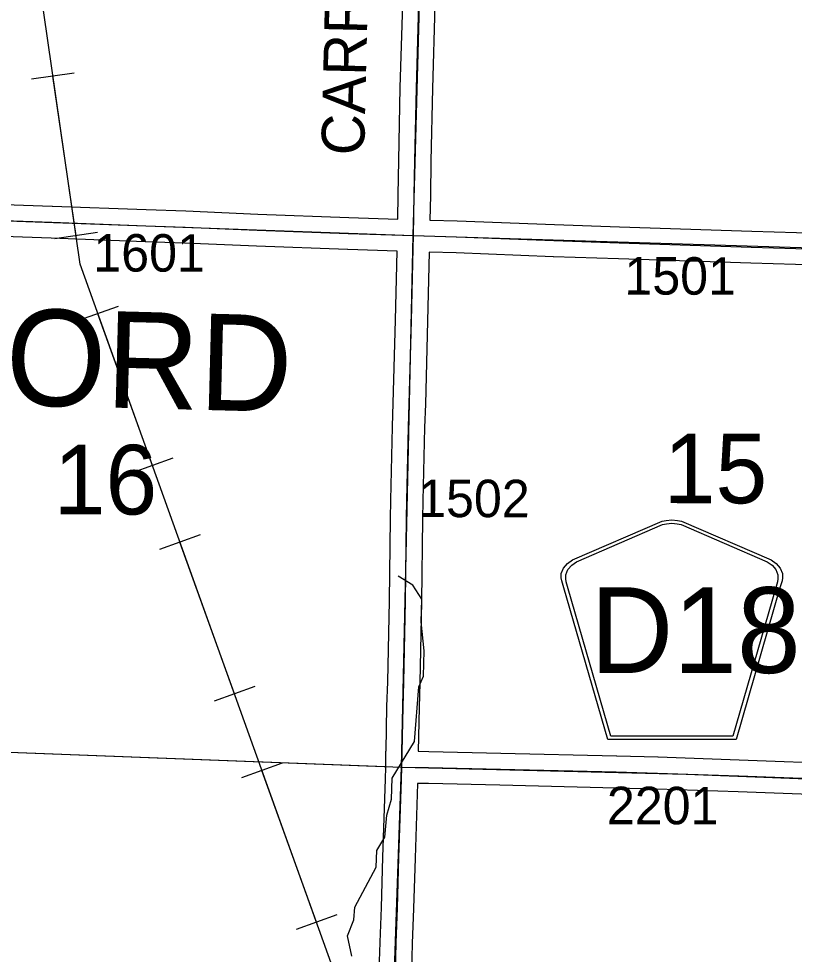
# Model space of a CAD drawing. Extents: x -157.2 to -99.3, y 12.2 to 46.2.
# Drawn here: x -142.209 to -140.761, y 37.727 to 39.474 of the extents above; entities that cross this region are included whole.
import ezdxf

# ---------------------------------------------------------------- set-up
doc = ezdxf.new("R2010")
doc.units = 0
for name, color, linetype in [('tdCoHydroRiver', 7, 'Continuous'), ('tdCoPipe', 7, 'Continuous'), ('tdCoSecRdNmbr', 7, 'Continuous'), ('tdCoSecRdTxt', 7, 'Continuous'), ('tdCoSecRteBand', 7, 'Continuous'), ('tdCoSecRteCL', 7, 'Continuous'), ('tdCoSectLine', 7, 'Continuous'), ('tdCoSectLinePart', 7, 'Continuous'), ('tdCoSectNmbr', 7, 'Continuous'), ('tdCoShieldCoRte', 7, 'Continuous'), ('tdCoSurfGravel', 7, 'Continuous'), ('tdCoTwpNameTxt', 7, 'Continuous')]:
    doc.layers.add(name, color=color, linetype=linetype)

msp = doc.modelspace()

# ---------------------------------------------------------------- linework, layer by layer
at = {"layer": 'tdCoHydroRiver'}
msp.add_lwpolyline([(-141.587, 37.7239), (-141.5954, 37.7621), (-141.5836, 37.7918), (-141.5814, 37.8154), (-141.5415, 37.89), (-141.5407, 37.9215), (-141.5258, 37.9463), (-141.5216, 37.9873), (-141.5129, 38.017), (-141.5118, 38.0565), (-141.4701, 38.1245), (-141.462, 38.2268), (-141.4534, 38.247), (-141.4519, 38.2943), (-141.458, 38.3482), (-141.4566, 38.3907), (-141.4731, 38.4165), (-141.5009, 38.4332)], dxfattribs=at)
at = {"layer": 'tdCoPipe'}
for p, q in [((-142.1052, 39.3728), (-142.1849, 39.3612)), ((-142.0619, 39.075), (-142.1415, 39.0634)), ((-142.023, 38.9371), (-142.0988, 38.9099)), ((-141.9213, 38.6538), (-141.997, 38.6266)), ((-141.87, 38.5107), (-141.9458, 38.4835)), ((-141.7683, 38.2274), (-141.844, 38.2002)), ((-141.717, 38.0843), (-141.7928, 38.0571)), ((-141.6153, 37.801), (-141.691, 37.7738))]:
    msp.add_line(p, q, dxfattribs=at)
for points in [[(-136.934, 22.5495), (-137.7242, 24.8933), (-138.4968, 27.1666), (-138.4114, 27.2635), (-138.4614, 27.8735), (-138.7227, 28.0895), (-138.7183, 28.4663), (-139.0397, 29.2926), (-139.1184, 29.8198), (-140.0614, 32.629), (-140.3902, 33.7747), (-140.3873, 34.3489), (-140.6033, 34.3601), (-141.0238, 35.5765), (-141.1818, 36.0085), (-141.3937, 37.236), (-141.4233, 37.6118), (-141.6227, 37.7022), (-142.0941, 39.016), (-142.2605, 40.1621), (-142.7574, 40.5833), (-142.8772, 41.3829)], [(-142.1018, 39.0692), (-142.145, 39.367)], [(-141.9592, 38.6402), (-142.0609, 38.9235)], [(-141.8062, 38.2138), (-141.9079, 38.4971)], [(-141.6532, 37.7874), (-141.7549, 38.0707)]]:
    msp.add_lwpolyline(points, dxfattribs=at)
at = {"layer": 'tdCoSecRteBand'}
for points in [[(-141.5014, 39.1003), (-141.5005, 39.1454), (-141.4995, 39.2093), (-141.4995, 39.2093), (-141.4995, 39.2094), (-141.4966, 39.3456), (-141.4966, 39.3457), (-141.4966, 39.3458), (-141.4921, 39.5016)], [(-141.4322, 39.4998), (-141.4366, 39.3442), (-141.4395, 39.2082), (-141.4405, 39.1445), (-141.4405, 39.1444), (-141.4405, 39.1443), (-141.4414, 39.0984), (-141.4411, 39.0984), (-141.3906, 39.0968), (-141.3905, 39.0968), (-141.3904, 39.0968), (-141.209, 39.0899), (-141.0875, 39.086), (-141.0874, 39.086), (-141.0874, 39.086), (-140.8406, 39.0778), (-140.6741, 39.0727)], [(-142.3068, 39.1301), (-142.1461, 39.1244), (-142.146, 39.1244), (-142.146, 39.1244), (-141.9707, 39.1178), (-141.897, 39.1153), (-141.8969, 39.1153), (-141.8968, 39.1153), (-141.7627, 39.1096), (-141.5927, 39.1032), (-141.5014, 39.1003)], [(-141.5358, 37.697), (-141.5343, 37.7495), (-141.5343, 37.7496), (-141.5343, 37.7498), (-141.5318, 37.815), (-141.5291, 37.9088), (-141.5291, 37.9089), (-141.5291, 37.909), (-141.5242, 38.0547), (-141.5237, 38.0771), (-141.5235, 38.1069), (-141.5231, 38.1069), (-141.5231, 38.1073), (-141.5215, 38.1899), (-141.5215, 38.1901), (-141.5215, 38.1903), (-141.52, 38.2362), (-141.5168, 38.3871), (-141.5151, 38.5413), (-141.5151, 38.5414), (-141.5151, 38.5414), (-141.5146, 38.575), (-141.5146, 38.5751), (-141.5146, 38.5752), (-141.5114, 38.7123), (-141.5114, 38.7125), (-141.5114, 38.7126), (-141.5099, 38.7564), (-141.5059, 38.9112), (-141.5026, 39.0404), (-141.5947, 39.0433), (-141.5948, 39.0433), (-141.5949, 39.0433), (-141.765, 39.0497), (-141.7651, 39.0497), (-141.7652, 39.0497), (-141.8992, 39.0554), (-141.9728, 39.0578), (-141.9728, 39.0578), (-141.9729, 39.0578), (-142.1482, 39.0645), (-142.3088, 39.0702)], [(-140.6758, 39.0127), (-140.8425, 39.0179), (-140.8425, 39.0179), (-140.8426, 39.0179), (-141.0894, 39.026), (-141.211, 39.03), (-141.2111, 39.03), (-141.2111, 39.03), (-141.3926, 39.0369), (-141.4427, 39.0385), (-141.446, 38.9096), (-141.4499, 38.7548), (-141.4499, 38.7546), (-141.4499, 38.7545), (-141.4514, 38.7108), (-141.4546, 38.5739), (-141.4551, 38.5406), (-141.4568, 38.3863), (-141.4568, 38.3861), (-141.4568, 38.386), (-141.46, 38.2348), (-141.46, 38.2346), (-141.46, 38.2345), (-141.4615, 38.1885), (-141.4631, 38.1064), (-141.4435, 38.1063), (-141.4433, 38.1063), (-141.4431, 38.1063), (-141.3092, 38.1031), (-141.0929, 38.0979), (-141.0929, 38.0979), (-141.0928, 38.0979), (-141.0159, 38.0959), (-141.0158, 38.0959), (-141.0156, 38.0959), (-140.864, 38.0907), (-140.8639, 38.0907), (-140.8639, 38.0907), (-140.6619, 38.0831)], [(-140.6644, 38.0231), (-140.8661, 38.0308), (-141.0176, 38.0359), (-141.0944, 38.0379), (-141.3106, 38.0431), (-141.4443, 38.0463), (-141.4643, 38.0465), (-141.4644, 38.0461), (-141.4644, 38.0461), (-141.4691, 37.907), (-141.4719, 37.8131), (-141.4719, 37.813), (-141.4719, 37.8128), (-141.4743, 37.7476), (-141.4758, 37.6953)]]:
    msp.add_lwpolyline(points, dxfattribs=at)
at = {"layer": 'tdCoSecRteCL'}
for points in [[(-141.472, 39.0694), (-141.4705, 39.1449), (-141.4695, 39.2088), (-141.4666, 39.3449), (-141.4621, 39.5008), (-141.4609, 39.5328), (-141.4565, 39.6847), (-141.4557, 39.7138), (-141.453, 39.8431), (-141.451, 39.8929), (-141.4461, 40.0364), (-141.4447, 40.0687)], [(-142.3079, 39.1001), (-142.1471, 39.0945), (-141.9718, 39.0878), (-141.898, 39.0853), (-141.7639, 39.0797), (-141.5937, 39.0733), (-141.472, 39.0694)], [(-141.4937, 38.0767), (-141.4915, 38.1893), (-141.49, 38.2354), (-141.4868, 38.3866), (-141.4851, 38.541), (-141.4846, 38.5745), (-141.4814, 38.7116), (-141.4799, 38.7555), (-141.476, 38.9104), (-141.4725, 39.0455), (-141.472, 39.0694)], [(-141.472, 39.0694), (-141.472, 39.0694), (-141.3915, 39.0668), (-141.21, 39.0599), (-141.0884, 39.056), (-140.8416, 39.0479), (-140.6749, 39.0427), (-140.4968, 39.0395), (-140.3126, 39.034), (-140.1321, 39.0303), (-139.9947, 39.0274), (-139.8581, 39.0249), (-139.6648, 39.0207), (-139.5585, 39.0178), (-139.4666, 39.0156)], [(-141.5433, 37.1241), (-141.5391, 37.1294), (-141.5339, 37.1383), (-141.529, 37.1494), (-141.5258, 37.1617), (-141.5238, 37.1738), (-141.5238, 37.1903), (-141.5208, 37.2483), (-141.5174, 37.3587), (-141.5147, 37.4226), (-141.51, 37.5696), (-141.5058, 37.6961), (-141.5043, 37.7486), (-141.5018, 37.814), (-141.4991, 37.9079), (-141.4942, 38.0539), (-141.4937, 38.0767)], [(-141.4937, 38.0767), (-141.4438, 38.0763), (-141.3099, 38.0731), (-141.0936, 38.0679), (-141.0167, 38.0659), (-140.865, 38.0608), (-140.663, 38.0531), (-140.5644, 38.0479), (-140.4961, 38.0456)]]:
    msp.add_lwpolyline(points, dxfattribs=at)
at = {"layer": 'tdCoSectLine'}
for points in [[(-141.4724, 39.0694), (-141.445, 40.0687)], [(-142.4709, 39.1056), (-141.4724, 39.0694)], [(-141.4941, 38.0767), (-141.4724, 39.0694)], [(-141.4724, 39.0694), (-140.4671, 39.0386)], [(-142.4882, 38.1148), (-141.4941, 38.0767)], [(-141.5284, 37.0843), (-141.4941, 38.0767)], [(-141.4941, 38.0767), (-140.9634, 38.064), (-140.4965, 38.0456)]]:
    msp.add_lwpolyline(points, dxfattribs=at)
at = {"layer": 'tdCoSectLinePart'}
msp.add_lwpolyline([(-142.4882, 38.1148), (-141.5241, 38.0778)], dxfattribs=at)
at = {"layer": 'tdCoShieldCoRte'}
for points in [[(-141.1096, 38.1285), (-141.1915, 38.4114), (-141.1954, 38.4245), (-141.1961, 38.4304), (-141.1961, 38.4382), (-141.1919, 38.4485), (-141.1846, 38.457), (-141.175, 38.4637), (-141.0078, 38.536), (-141.0002, 38.5377), (-140.9898, 38.5386), (-140.9794, 38.5377), (-140.9719, 38.536), (-140.8046, 38.4637), (-140.795, 38.457), (-140.7878, 38.4485), (-140.7835, 38.4382), (-140.7835, 38.4304), (-140.7842, 38.4245), (-140.7881, 38.4114), (-140.8701, 38.1285)], [(-141.1037, 38.1348), (-141.1835, 38.4101), (-141.1872, 38.4227), (-141.1879, 38.4283), (-141.1879, 38.4358), (-141.1838, 38.4457), (-141.1768, 38.4539), (-141.1676, 38.4603), (-141.007, 38.5298), (-140.9998, 38.5313), (-140.9898, 38.5322), (-140.9798, 38.5313), (-140.9726, 38.5298), (-140.812, 38.4603), (-140.8028, 38.4539), (-140.7958, 38.4457), (-140.7918, 38.4358), (-140.7918, 38.4283), (-140.7925, 38.4227), (-140.7962, 38.4101), (-140.8759, 38.1348)]]:
    msp.add_lwpolyline(points, close=True, dxfattribs=at)
at = {"layer": 'tdCoSurfGravel'}
for points in [[(-141.5058, 37.6961), (-141.5043, 37.7486), (-141.5018, 37.814), (-141.4991, 37.9079), (-141.4942, 38.0539), (-141.4937, 38.0767), (-141.4915, 38.1893), (-141.49, 38.2354), (-141.4868, 38.3866), (-141.4851, 38.541), (-141.4846, 38.5745), (-141.4814, 38.7116), (-141.4799, 38.7555), (-141.476, 38.9104), (-141.4725, 39.0455), (-141.472, 39.0694), (-141.4705, 39.1449), (-141.4695, 39.2088), (-141.4666, 39.3449), (-141.4621, 39.5008)], [(-142.5525, 39.1174), (-142.5464, 39.1142), (-142.5382, 39.1115), (-142.5274, 39.1085), (-142.5163, 39.1073), (-142.4768, 39.1058), (-142.3774, 39.1019), (-142.3079, 39.1001), (-142.1471, 39.0945), (-141.9718, 39.0878), (-141.898, 39.0853), (-141.7639, 39.0797), (-141.5937, 39.0733), (-141.472, 39.0694), (-141.472, 39.0694)], [(-141.472, 39.0694), (-141.3915, 39.0668), (-141.21, 39.0599), (-141.0884, 39.056), (-140.8416, 39.0479), (-140.6749, 39.0427), (-140.4968, 39.0395), (-140.3126, 39.034), (-140.1321, 39.0303), (-139.9947, 39.0274), (-139.8581, 39.0249), (-139.6648, 39.0207), (-139.5585, 39.0178), (-139.4666, 39.0156)], [(-141.4937, 38.0767), (-141.4438, 38.0763), (-141.3099, 38.0731), (-141.0936, 38.0679), (-141.0167, 38.0659), (-140.865, 38.0608), (-140.663, 38.0531)]]:
    msp.add_lwpolyline(points, dxfattribs=at)

# ---------------------------------------------------------------- texts
at = {"layer": 'tdCoSecRdNmbr'}
for s, rotation, p in [('1601', 359.8915, (-142.0696, 39.0023)), ('1501', 359.8923, (-141.0785, 38.9593)), ('1502', 359.892, (-141.4634, 38.5438)), ('2201', 359.8923, (-141.1111, 37.9704))]:
    msp.add_text(s, height=0.07, rotation=rotation, dxfattribs=at).set_placement(p)
at = {"layer": 'tdCoSecRdTxt'}
msp.add_text('CARROLL AVE', height=0.08, rotation=88.641, dxfattribs=at).set_placement((-141.5642, 39.2185))
at = {"layer": 'tdCoSectNmbr'}
for s, rotation, p in [('15', 359.8923, (-141.0052, 38.5698)), ('16', 359.8915, (-142.1437, 38.5489))]:
    msp.add_text(s, height=0.13, rotation=rotation, dxfattribs=at).set_placement(p)
at = {"layer": 'tdCoShieldCoRte'}
msp.add_text('D18', height=0.16, dxfattribs=at).set_placement((-141.1418, 38.2527))
at = {"layer": 'tdCoTwpNameTxt'}
msp.add_text('CONCORD', height=0.18, rotation=358.5196, dxfattribs=at).set_placement((-142.9433, 38.7717))

doc.saveas('drawing.dxf')
